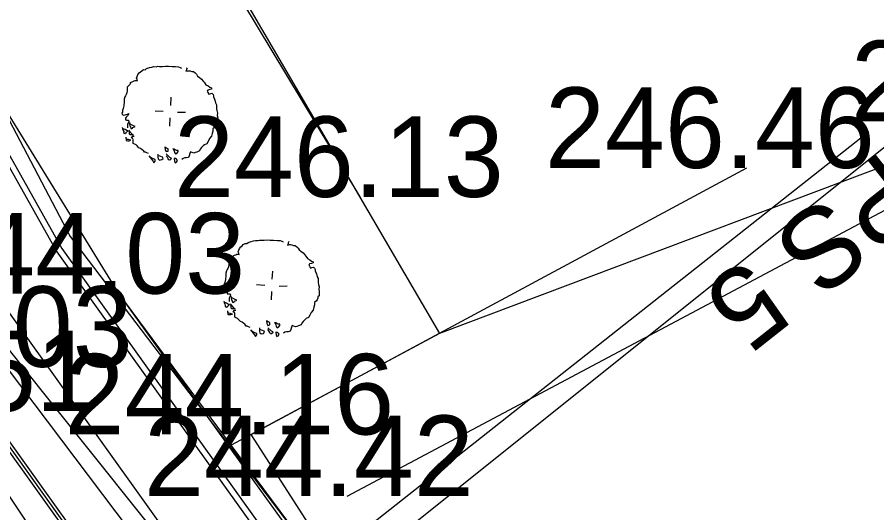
# Model space of a CAD drawing. Extents: x -601754 to -601440, y -1201912 to -1200862.
# Drawn here: x -601616.59 to -601595.26, y -1200964.76 to -1200952.45 of the extents above; entities that cross this region are included whole.
import ezdxf

# ---------------------------------------------------------------- set-up
doc = ezdxf.new("R2010")
doc.units = 0
for name, color, linetype in [('Hranice parcel', 7, 'Continuous'), ('u_drén', 7, 'Continuous'), ('u_hrany', 7, 'Continuous'), ('u_návrh', 7, 'Continuous'), ('u_oblouky', 7, 'Continuous'), ('u_osa', 7, 'Continuous'), ('u_pricne_cesta', 7, 'Continuous'), ('u_terénní úpravy', 7, 'Continuous'), ('u_vysadba_SO_101', 7, 'Continuous'), ('u_vyska', 7, 'Continuous')]:
    doc.layers.add(name, color=color, linetype=linetype)

msp = doc.modelspace()

# ---------------------------------------------------------------- linework, layer by layer
at = {"layer": 'Hranice parcel'}
for p, q in [((-601610.96, -1200951.99), (-601606.11, -1200960.3)), ((-601606.11, -1200960.3), (-601611.28, -1200963.08))]:
    msp.add_line(p, q, dxfattribs=at)
for points in [[(-601611.28, -1200963.08), (-601614.07, -1200959.31), (-601621.9, -1200946.57), (-601626.39, -1200937.08), (-601630.02, -1200926.25), (-601631.65, -1200918.55), (-601633.57, -1200899.96), (-601633.33, -1200887.98), (-601632.07, -1200885.6), (-601629.11, -1200882.26)], [(-601468.497, -1200893.491), (-601543.98, -1200933.91), (-601563.17, -1200944.1), (-601606.11, -1200960.3)], [(-601589.41, -1200989.76), (-601594.55, -1200983.92), (-601604.39, -1200972.37), (-601611.28, -1200963.08)]]:
    msp.add_lwpolyline(points, dxfattribs=at)
at = {"layer": 'u_drén'}
msp.add_lwpolyline([(-601630.738, -1200933.27), (-601628.676, -1200940.153), (-601624.291, -1200950.498), (-601618.798, -1200960.3), (-601612.295, -1200969.398), (-601587.744, -1201000.039)], dxfattribs=at)
at = {"layer": 'u_hrany'}
for points in [[(-601637.65, -1200892.44), (-601636.56, -1200901.01), (-601634.78, -1200919.25), (-601632.6, -1200928.32), (-601629.33, -1200937.82), (-601624.51, -1200947.91), (-601616.86, -1200961.13), (-601606.97, -1200974.25), (-601596.82, -1200985.88), (-601582.46, -1201002.22), (-601574.49, -1201012.64), (-601569.33, -1201022.81), (-601566.79, -1201038.25), (-601566.21, -1201048.21)], [(-601568.57, -1201015.08), (-601571.45, -1201010.54), (-601577.11, -1201003.42), (-601594.37, -1200984.29), (-601604.5, -1200972.6), (-601614.07, -1200959.31), (-601621.9, -1200946.57), (-601626.39, -1200937.08), (-601629.97, -1200926.48)], [(-601621.22, -1200935.1), (-601608.09, -1200956.91)], [(-601629.33, -1200937.82), (-601626.28, -1200948.41), (-601618.2, -1200962.23), (-601609.12, -1200975.86), (-601600.84, -1200990.01)], [(-601608.4, -1200964.34), (-601590.91, -1200955.03)], [(-601604.5, -1200972.6), (-601610.78, -1200962.81), (-601598.49, -1200956.19)]]:
    msp.add_lwpolyline(points, dxfattribs=at)
at = {"layer": 'u_návrh'}
for points in [[(-601634.025, -1200887.577), (-601630.185, -1200917.812), (-601628.225, -1200928.505), (-601625.119, -1200938.871), (-601620.896, -1200948.834), (-601615.607, -1200958.274), (-601609.285, -1200967.119), (-601584.73, -1200997.764)], [(-601633.876, -1200887.558), (-601630.036, -1200917.789), (-601628.079, -1200928.47), (-601624.978, -1200938.82), (-601620.761, -1200948.768), (-601615.48, -1200958.194), (-601609.165, -1200967.028), (-601578.723, -1201005.021)], [(-601637.844, -1200888.062), (-601633.991, -1200918.402), (-601631.974, -1200929.408), (-601628.747, -1200940.179), (-601624.358, -1200950.531), (-601618.862, -1200960.341), (-601612.355, -1200969.444), (-601581.832, -1201007.537)], [(-601637.695, -1200888.043), (-601633.842, -1200918.379), (-601631.828, -1200929.372), (-601628.605, -1200940.128), (-601624.223, -1200950.465), (-601618.735, -1200960.26), (-601612.236, -1200969.353), (-601587.617, -1201000.078)]]:
    msp.add_lwpolyline(points, dxfattribs=at)
at = {"layer": 'u_oblouky'}
for q in [(-601580.365, -1200943.882), (-601628.449, -1200946.159)]:
    msp.add_line((-601610.76, -1200968.236), q, dxfattribs=at)
at = {"layer": 'u_osa'}
msp.add_lwpolyline([(-601635.86, -1200887.81), (-601632.013, -1200918.095), (-601630.026, -1200928.939), (-601626.862, -1200939.5), (-601622.56, -1200949.65), (-601617.171, -1200959.267), (-601610.76, -1200968.236), (-601578.672, -1201008.284), (-601575.031, -1201013.469), (-601572.075, -1201019.074), (-601569.852, -1201025.007), (-601568.398, -1201031.174), (-601566.15, -1201044.408), (-601565.576, -1201049.148), (-601565.456, -1201053.922), (-601565.793, -1201058.685), (-601566.228, -1201062.343), (-601567.198, -1201067.854), (-601568.778, -1201073.221), (-601570.948, -1201078.378), (-601573.681, -1201083.261), (-601575.226, -1201085.692), (-601578.132, -1201090.011)], dxfattribs=at)
at = {"layer": 'u_pricne_cesta'}
msp.add_lwpolyline([(-601595.458, -1200955.29), (-601611.149, -1200967.692), (-601626.84, -1200980.093)], dxfattribs=at)
at = {"layer": 'u_terénní úpravy'}
msp.add_lwpolyline([(-601623.651, -1200937.04), (-601622.862, -1200939.893), (-601618.936, -1200950.908), (-601615.274, -1200957.893), (-601609.075, -1200966.053), (-601604.07, -1200972.745), (-601597.484, -1200980.476), (-601592.22, -1200988.176), (-601585.958, -1200994.904), (-601578.723, -1201005.021), (-601574.41, -1201008.093), (-601573.524, -1201008.969), (-601571.743, -1201011.837), (-601569.512, -1201016.171), (-601566.023, -1201016.188)], dxfattribs=at)
at = {"layer": 'u_vysadba_SO_101'}
for points in [[(-601613.78, -1200954.097), (-601613.778, -1200954.068), (-601613.718, -1200954.042), (-601613.688, -1200954.029), (-601613.658, -1200954.016), (-601613.629, -1200954.017), (-601613.6, -1200954.019), (-601613.613, -1200953.989), (-601613.626, -1200953.959), (-601613.609, -1200953.916), (-601613.592, -1200953.873), (-601613.561, -1200953.831), (-601613.53, -1200953.803), (-601613.499, -1200953.775), (-601613.454, -1200953.748), (-601613.41, -1200953.751), (-601613.379, -1200953.723), (-601613.305, -1200953.698), (-601613.246, -1200953.686), (-601613.201, -1200953.674), (-601613.143, -1200953.677), (-601613.098, -1200953.665), (-601613.054, -1200953.667), (-601612.981, -1200953.671), (-601612.908, -1200953.66), (-601612.834, -1200953.664), (-601612.747, -1200953.669), (-601612.659, -1200953.673), (-601612.586, -1200953.677), (-601612.543, -1200953.694), (-601612.515, -1200953.71)], [(-601612.368, -1200953.703), (-601612.384, -1200953.732), (-601612.386, -1200953.761), (-601612.402, -1200953.789), (-601612.357, -1200953.777), (-601612.328, -1200953.779), (-601612.299, -1200953.78), (-601612.256, -1200953.797), (-601612.212, -1200953.799), (-601612.17, -1200953.831), (-601612.142, -1200953.862), (-601612.115, -1200953.907), (-601612.073, -1200953.939), (-601612.017, -1200953.985), (-601611.975, -1200954.032), (-601611.948, -1200954.062), (-601611.907, -1200954.123), (-601611.85, -1200954.155), (-601611.808, -1200954.187), (-601611.765, -1200954.204), (-601611.766, -1200954.233)], [(-601613.78, -1200954.097), (-601613.781, -1200954.112), (-601613.827, -1200954.153), (-601613.858, -1200954.181), (-601613.86, -1200954.225), (-601613.862, -1200954.269), (-601613.865, -1200954.327), (-601613.882, -1200954.37), (-601613.898, -1200954.399), (-601613.914, -1200954.427), (-601613.932, -1200954.485), (-601613.934, -1200954.514), (-601613.937, -1200954.572), (-601613.939, -1200954.616), (-601613.941, -1200954.645), (-601613.959, -1200954.717), (-601613.976, -1200954.761), (-601613.978, -1200954.804), (-601613.994, -1200954.833), (-601613.981, -1200954.863), (-601613.938, -1200954.88), (-601613.849, -1200954.855), (-601613.819, -1200954.842), (-601613.852, -1200954.899), (-601613.882, -1200954.927), (-601613.898, -1200954.955), (-601613.901, -1200954.999), (-601613.872, -1200955), (-601613.828, -1200955.003), (-601613.815, -1200955.033), (-601613.832, -1200955.076), (-601613.848, -1200955.104), (-601613.85, -1200955.148), (-601613.852, -1200955.192)], [(-601612.78, -1200954.639), (-601612.77, -1200954.434)], [(-601611.766, -1200954.233), (-601611.811, -1200954.245), (-601611.856, -1200954.258), (-601611.872, -1200954.286), (-601611.859, -1200954.316), (-601611.832, -1200954.361), (-601611.802, -1200954.348), (-601611.757, -1200954.336), (-601611.729, -1200954.367), (-601611.716, -1200954.397), (-601611.718, -1200954.426), (-601611.692, -1200954.486), (-601611.68, -1200954.53), (-601611.667, -1200954.575), (-601611.64, -1200954.62), (-601611.642, -1200954.65), (-601611.644, -1200954.693), (-601611.646, -1200954.723), (-601611.634, -1200954.767), (-601611.622, -1200954.826), (-601611.625, -1200954.885), (-601611.614, -1200954.944), (-601611.615, -1200954.973), (-601611.617, -1200955.002), (-601611.619, -1200955.046), (-601611.65, -1200955.074), (-601611.651, -1200955.103), (-601611.668, -1200955.146), (-601611.684, -1200955.174), (-601611.73, -1200955.216), (-601611.734, -1200955.274), (-601611.751, -1200955.332), (-601611.77, -1200955.404), (-601611.817, -1200955.46), (-601611.85, -1200955.532), (-601611.882, -1200955.589), (-601611.942, -1200955.615), (-601611.973, -1200955.642), (-601612.019, -1200955.684), (-601612.05, -1200955.726), (-601612.067, -1200955.769), (-601612.127, -1200955.795), (-601612.172, -1200955.808), (-601612.202, -1200955.821), (-601612.245, -1200955.804), (-601612.288, -1200955.787), (-601612.305, -1200955.83), (-601612.322, -1200955.888), (-601612.339, -1200955.931), (-601612.384, -1200955.943), (-601612.428, -1200955.941)], [(-601612.964, -1200954.79), (-601613.168, -1200954.779)], [(-601612.614, -1200954.809), (-601612.408, -1200954.805)], [(-601613.802, -1200955.063), (-601613.804, -1200955.106), (-601613.791, -1200955.136), (-601613.779, -1200955.181), (-601613.765, -1200955.211), (-601613.736, -1200955.212), (-601613.72, -1200955.184), (-601613.66, -1200955.158), (-601613.703, -1200955.141), (-601613.732, -1200955.125), (-601613.789, -1200955.093)], [(-601612.797, -1200954.945), (-601612.807, -1200955.15)], [(-601613.984, -1200955.185), (-601613.971, -1200955.215), (-601613.958, -1200955.259), (-601613.945, -1200955.289), (-601613.947, -1200955.318), (-601613.918, -1200955.335), (-601613.888, -1200955.307), (-601613.842, -1200955.265), (-601613.871, -1200955.264), (-601613.913, -1200955.232), (-601613.956, -1200955.215)], [(-601613.826, -1200955.252), (-601613.785, -1200955.298), (-601613.743, -1200955.344), (-601613.701, -1200955.375)], [(-601613.701, -1200955.375), (-601613.73, -1200955.374), (-601613.759, -1200955.372), (-601613.789, -1200955.371), (-601613.802, -1200955.341), (-601613.8, -1200955.312), (-601613.813, -1200955.282)], [(-601613.894, -1200955.424), (-601613.884, -1200955.512), (-601613.84, -1200955.514), (-601613.811, -1200955.516), (-601613.766, -1200955.504), (-601613.824, -1200955.486), (-601613.868, -1200955.484), (-601613.881, -1200955.454)], [(-601613.33, -1200955.834), (-601613.373, -1200955.817), (-601613.401, -1200955.801), (-601613.431, -1200955.8), (-601613.457, -1200955.754), (-601613.486, -1200955.738), (-601613.528, -1200955.707), (-601613.571, -1200955.69), (-601613.613, -1200955.644), (-601613.64, -1200955.613), (-601613.712, -1200955.58), (-601613.709, -1200955.536), (-601613.707, -1200955.492), (-601613.72, -1200955.462), (-601613.749, -1200955.446), (-601613.717, -1200955.404), (-601613.688, -1200955.405)], [(-601612.926, -1200955.665), (-601612.915, -1200955.739), (-601612.888, -1200955.784), (-601612.843, -1200955.772), (-601612.842, -1200955.743), (-601612.84, -1200955.714), (-601612.883, -1200955.697), (-601612.912, -1200955.681)], [(-601612.723, -1200955.705), (-601612.697, -1200955.765), (-601612.684, -1200955.81), (-601612.657, -1200955.841), (-601612.627, -1200955.828), (-601612.595, -1200955.785), (-601612.594, -1200955.756), (-601612.637, -1200955.754), (-601612.666, -1200955.738), (-601612.694, -1200955.721), (-601612.723, -1200955.72)], [(-601613.318, -1200955.893), (-601613.222, -1200956.016), (-601613.195, -1200956.061), (-601613.164, -1200956.019), (-601613.162, -1200955.99), (-601613.191, -1200955.973), (-601613.234, -1200955.957), (-601613.262, -1200955.94), (-601613.291, -1200955.924)], [(-601613.096, -1200955.847), (-601613.1, -1200955.92), (-601613.088, -1200955.964), (-601613.06, -1200955.995), (-601613.001, -1200955.983), (-601612.97, -1200955.956), (-601612.983, -1200955.926), (-601613.026, -1200955.909), (-601613.069, -1200955.892)], [(-601612.891, -1200955.843), (-601612.807, -1200955.92), (-601612.779, -1200955.937), (-601612.766, -1200955.967), (-601612.797, -1200955.994), (-601612.826, -1200955.993), (-601612.839, -1200955.963), (-601612.866, -1200955.917), (-601612.893, -1200955.887)], [(-601612.692, -1200955.956), (-601612.681, -1200956.03), (-601612.668, -1200956.06), (-601612.638, -1200956.047), (-601612.607, -1200956.004), (-601612.634, -1200955.974), (-601612.663, -1200955.957), (-601612.692, -1200955.956)], [(-601612.428, -1200955.941), (-601612.472, -1200955.953), (-601612.503, -1200955.98)], [(-601611.258, -1200958.415), (-601611.257, -1200958.386), (-601611.197, -1200958.36), (-601611.167, -1200958.346), (-601611.137, -1200958.333), (-601611.108, -1200958.335), (-601611.078, -1200958.337), (-601611.091, -1200958.307), (-601611.104, -1200958.277), (-601611.088, -1200958.234), (-601611.071, -1200958.19), (-601611.039, -1200958.148), (-601611.008, -1200958.121), (-601610.978, -1200958.093), (-601610.932, -1200958.066), (-601610.888, -1200958.068), (-601610.858, -1200958.041), (-601610.783, -1200958.015), (-601610.724, -1200958.004), (-601610.679, -1200957.992), (-601610.621, -1200957.995), (-601610.576, -1200957.982), (-601610.533, -1200957.985), (-601610.46, -1200957.988), (-601610.386, -1200957.978), (-601610.313, -1200957.982), (-601610.225, -1200957.986), (-601610.138, -1200957.991), (-601610.065, -1200957.995), (-601610.022, -1200958.012), (-601609.993, -1200958.028)], [(-601609.846, -1200958.021), (-601609.862, -1200958.049), (-601609.864, -1200958.079), (-601609.88, -1200958.107), (-601609.836, -1200958.095), (-601609.806, -1200958.096), (-601609.777, -1200958.098), (-601609.734, -1200958.115), (-601609.69, -1200958.117), (-601609.648, -1200958.148), (-601609.62, -1200958.179), (-601609.594, -1200958.225), (-601609.551, -1200958.256), (-601609.495, -1200958.303), (-601609.454, -1200958.349), (-601609.426, -1200958.38), (-601609.385, -1200958.441), (-601609.328, -1200958.473), (-601609.286, -1200958.504), (-601609.243, -1200958.521), (-601609.245, -1200958.551)], [(-601611.258, -1200958.415), (-601611.259, -1200958.429), (-601611.305, -1200958.471), (-601611.336, -1200958.499), (-601611.338, -1200958.542), (-601611.34, -1200958.586), (-601611.344, -1200958.645), (-601611.36, -1200958.688), (-601611.377, -1200958.716), (-601611.393, -1200958.745), (-601611.41, -1200958.802), (-601611.412, -1200958.831), (-601611.415, -1200958.89), (-601611.417, -1200958.934), (-601611.419, -1200958.963), (-601611.437, -1200959.035), (-601611.454, -1200959.078), (-601611.457, -1200959.122), (-601611.473, -1200959.15), (-601611.46, -1200959.18), (-601611.417, -1200959.197), (-601611.328, -1200959.173), (-601611.298, -1200959.16), (-601611.33, -1200959.216), (-601611.361, -1200959.244), (-601611.377, -1200959.273), (-601611.379, -1200959.316), (-601611.35, -1200959.318), (-601611.306, -1200959.32), (-601611.293, -1200959.35), (-601611.31, -1200959.393), (-601611.326, -1200959.422), (-601611.328, -1200959.465), (-601611.331, -1200959.509)], [(-601609.245, -1200958.551), (-601609.289, -1200958.563), (-601609.334, -1200958.575), (-601609.35, -1200958.604), (-601609.337, -1200958.634), (-601609.31, -1200958.679), (-601609.28, -1200958.666), (-601609.235, -1200958.654), (-601609.208, -1200958.684), (-601609.195, -1200958.714), (-601609.196, -1200958.743), (-601609.17, -1200958.803), (-601609.158, -1200958.848), (-601609.146, -1200958.893), (-601609.119, -1200958.938), (-601609.12, -1200958.967), (-601609.123, -1200959.011), (-601609.124, -1200959.04), (-601609.112, -1200959.085), (-601609.1, -1200959.144), (-601609.103, -1200959.202), (-601609.092, -1200959.261), (-601609.093, -1200959.291), (-601609.095, -1200959.32), (-601609.097, -1200959.364), (-601609.128, -1200959.391), (-601609.13, -1200959.421), (-601609.146, -1200959.464), (-601609.163, -1200959.492), (-601609.209, -1200959.533), (-601609.212, -1200959.592), (-601609.23, -1200959.65), (-601609.248, -1200959.722), (-601609.295, -1200959.778), (-601609.328, -1200959.849), (-601609.36, -1200959.906), (-601609.42, -1200959.932), (-601609.451, -1200959.96), (-601609.497, -1200960.001), (-601609.529, -1200960.044), (-601609.545, -1200960.087), (-601609.605, -1200960.113), (-601609.65, -1200960.125), (-601609.68, -1200960.138), (-601609.723, -1200960.121), (-601609.766, -1200960.104), (-601609.783, -1200960.147), (-601609.801, -1200960.205), (-601609.818, -1200960.248), (-601609.862, -1200960.26), (-601609.906, -1200960.258)], [(-601610.259, -1200958.956), (-601610.248, -1200958.752)], [(-601610.442, -1200959.108), (-601610.647, -1200959.097)], [(-601610.092, -1200959.126), (-601609.887, -1200959.122)], [(-601610.275, -1200959.263), (-601610.286, -1200959.467)], [(-601611.462, -1200959.502), (-601611.449, -1200959.532), (-601611.437, -1200959.577), (-601611.424, -1200959.607), (-601611.425, -1200959.636), (-601611.397, -1200959.652), (-601611.366, -1200959.625), (-601611.32, -1200959.583), (-601611.349, -1200959.581), (-601611.391, -1200959.55), (-601611.434, -1200959.533)], [(-601611.28, -1200959.38), (-601611.282, -1200959.424), (-601611.269, -1200959.454), (-601611.257, -1200959.498), (-601611.244, -1200959.528), (-601611.215, -1200959.53), (-601611.198, -1200959.502), (-601611.139, -1200959.475), (-601611.182, -1200959.459), (-601611.21, -1200959.442), (-601611.267, -1200959.41)], [(-601611.372, -1200959.741), (-601611.362, -1200959.83), (-601611.318, -1200959.832), (-601611.289, -1200959.834), (-601611.245, -1200959.821), (-601611.302, -1200959.804), (-601611.346, -1200959.801), (-601611.359, -1200959.771)], [(-601611.305, -1200959.569), (-601611.263, -1200959.615), (-601611.222, -1200959.661), (-601611.179, -1200959.693)], [(-601611.179, -1200959.693), (-601611.208, -1200959.691), (-601611.238, -1200959.69), (-601611.267, -1200959.688), (-601611.28, -1200959.658), (-601611.278, -1200959.629), (-601611.291, -1200959.599)], [(-601610.808, -1200960.152), (-601610.851, -1200960.135), (-601610.88, -1200960.119), (-601610.909, -1200960.117), (-601610.936, -1200960.072), (-601610.964, -1200960.056), (-601611.006, -1200960.024), (-601611.049, -1200960.007), (-601611.091, -1200959.961), (-601611.119, -1200959.93), (-601611.19, -1200959.897), (-601611.188, -1200959.854), (-601611.185, -1200959.81), (-601611.199, -1200959.78), (-601611.227, -1200959.764), (-601611.195, -1200959.721), (-601611.166, -1200959.723)], [(-601610.575, -1200960.164), (-601610.578, -1200960.237), (-601610.566, -1200960.282), (-601610.538, -1200960.312), (-601610.479, -1200960.301), (-601610.449, -1200960.273), (-601610.462, -1200960.243), (-601610.505, -1200960.226), (-601610.548, -1200960.21)], [(-601610.404, -1200959.983), (-601610.393, -1200960.057), (-601610.366, -1200960.102), (-601610.322, -1200960.09), (-601610.32, -1200960.06), (-601610.319, -1200960.031), (-601610.362, -1200960.014), (-601610.39, -1200959.998)], [(-601610.369, -1200960.16), (-601610.286, -1200960.238), (-601610.257, -1200960.254), (-601610.244, -1200960.284), (-601610.275, -1200960.312), (-601610.304, -1200960.31), (-601610.317, -1200960.28), (-601610.344, -1200960.235), (-601610.372, -1200960.204)], [(-601610.201, -1200960.023), (-601610.175, -1200960.083), (-601610.163, -1200960.127), (-601610.135, -1200960.158), (-601610.105, -1200960.145), (-601610.073, -1200960.103), (-601610.072, -1200960.074), (-601610.116, -1200960.071), (-601610.144, -1200960.055), (-601610.173, -1200960.039), (-601610.202, -1200960.037)], [(-601610.797, -1200960.211), (-601610.701, -1200960.333), (-601610.674, -1200960.379), (-601610.642, -1200960.336), (-601610.641, -1200960.307), (-601610.669, -1200960.291), (-601610.712, -1200960.274), (-601610.741, -1200960.258), (-601610.769, -1200960.242)], [(-601610.17, -1200960.273), (-601610.16, -1200960.347), (-601610.147, -1200960.377), (-601610.117, -1200960.364), (-601610.085, -1200960.322), (-601610.113, -1200960.291), (-601610.141, -1200960.275), (-601610.17, -1200960.273)], [(-601609.906, -1200960.258), (-601609.951, -1200960.27), (-601609.981, -1200960.298)]]:
    msp.add_lwpolyline(points, dxfattribs=at)

# ---------------------------------------------------------------- texts
at = {"layer": 'u_pricne_cesta'}
msp.add_text('PS 5', height=2, rotation=218.3223, dxfattribs=at).set_placement((-601595.131, -1200955.704))
at = {"layer": 'u_vyska'}
for s, p in [('247.37', (-601595.903, -1200955.03)), ('246.46', (-601603.492, -1200956.19)), ('246.13', (-601612.697, -1200956.91)), ('244.03', (-601619.113, -1200959.31)), ('244.03', (-601621.903, -1200961.13)), ('243.51', (-601622.815, -1200962.23)), ('244.16', (-601615.415, -1200962.81)), ('244.42', (-601613.44, -1200964.34))]:
    msp.add_text(s, height=2, dxfattribs=at).set_placement(p)

doc.saveas('drawing.dxf')
